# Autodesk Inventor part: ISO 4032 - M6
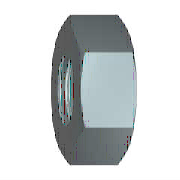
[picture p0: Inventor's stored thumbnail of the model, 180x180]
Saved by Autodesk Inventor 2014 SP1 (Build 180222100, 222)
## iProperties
Created: 2013-02
Part Number: ISO 4032 - M6
Material: Stainless Steel, 440C
Description: Hexagon nuts, style 1 - Product grades A and B
Document SubType Name: Modeling
Standard: ISO 4032
Designer: SFC
Standard Revision: Third edition 1999-08-15
Standards Organization: ISO
Language: en-US
Size Designation: M6
Categories: <MemberInstance><Categories><Category DisplayName="Fasteners" InternalName="e4da775c-781d-43d5-af7c-5136215cf5a6" Mnemonic="FSTN"><Category DisplayName="Nuts" I
Density: 7.75 g/cm^3
Appearance: Semi-Polished
IsCustomPart: 0
Author: SFC
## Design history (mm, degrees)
body "Solid1"
sketch "Sketch1"
  geometry: L1 (-5.774, 0)-(-2.887, 5); L2 (-2.887, 5)-(2.887, 5); L3 (2.887, 5)-(5.774, 0); L4 (5.774, 0)-(2.887, -5); L5 (2.887, -5)-(-2.887, -5); L6 (-2.887, -5)-(-5.774, 0); 2 further points
  constraints: 12 end point, 1 coincident, 1 horizontal, 11 other
  dimensions: "d0" = 11.54701 distance of L3.end L1.start (= 1.1547 x SW)
workaxis "Work Axis1"
workplane "Work Plane1"
extrude "Body" new body sketch "Sketch1" distance "d1" = 5.2 (= KOH); taper "d2" = 0 deg
sketch "Sketch2"
  geometry: L1 (0, 2.887)-(0, 5.774) reference; L2 (0, 5.774)-(5.2, 5.774) reference; L3 (5.2, 2.887)-(5.2, 5.774) reference; L4 (-1.04, 0)-(6.24, 0) reference; L5 (0.764, 5.774)-(0, 4.45); L6 (4.436, 5.774)-(5.2, 4.45)
  constraints: 4 end point, 4 point on line
  dimensions: "d3" = 30 deg angle of L1 L5 (= ANG1); "d4" = 30 deg angle of L3 L6 (= ANG2); "d5" = 8.9 diameter of L5.end L4 (= SW0); "d6" = 8.9 diameter of L6.end L4 (= SW01)
revolve "Chamfer1" stored, may be unused: angle "d7" = 90 deg
sketch "Sketch3"
  geometry: 4 further points
  constraints: 1 coincident, 1 other
hole "Thread" sketch "Sketch3" diameter "d25" = 4.917; stored, may be unused: countersink angle "d29" = 82 deg, drill point angle "d31" = 118 deg; dims "d26" = 6, "d27" = 4, "d28" = 2, "d30" = 8
chamfer "Chamfer2" distance "d8" = 0.54127 (= -0.5 x GD1 + 0.5 x NND); stored, may be unused: angle "d9" = 30 deg, second distance "d40" = 0.54127 (= -0.5 x GD1 + 0.5 x NND)
chamfer "Chamfer3" distance "d10" = 0.54127 (= -0.5 x GD1 + 0.5 x NND); stored, may be unused: angle "d11" = 30 deg, second distance "d41" = 0.54127 (= -0.5 x GD1 + 0.5 x NND)
other parameters: "ANG1" = 30 deg [user parameter; used in 1 equation term], "ANG2" = 30 deg [user parameter; used in 1 equation term], "NND" = 6 [user parameter; used in 4 equation terms], "KOH" = 5.2 [user parameter; used in 1 equation term], "SW0" = 8.9 [user parameter; used in 2 equation terms], "SW01" = 8.9 (= SW0) [user parameter; used in 1 equation term], "GD1" = 4.91747 (computed from THREADDIA, PTC, TOA) [user parameter; used in 4 equation terms], "d13" = 0, "d14" = 0, "d39" = 0, "d42" = 0, "GUL" = 0.54127 (= 0.541266 x PTC) [user parameter], "THREADDIA" = 6 [user parameter; used in 1 equation term], "TOA" = 30 deg [user parameter; used in 1 equation term], "PTC" = 1 [user parameter; used in 4 equation terms], "E0" = 11.55 (= 1.155 x SW) [user parameter], "GAL" = 0.54127 (= 0.541266 x PTC) [user parameter]
